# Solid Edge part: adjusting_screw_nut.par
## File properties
Title: Adjusting screw nut
Author: Abhinav Rai
Template: Normal.par
Last saved by: CADCIM
Revision: 19
Application: Solid Edge
Accuracy: 0.99
Material: aluminum
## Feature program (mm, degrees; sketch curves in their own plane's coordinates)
sketch for "unnamed RevolvedProtrusion 1" plane through (0, 0, 0) normal (0, -1, 0) x-axis (1, 0, 0)
  line (25.4, 9.7462) -> (74.676, 9.7462)
  line (76.2, 8.2222) -> (74.676, 9.7462)
  line (76.2, -26.8298) -> (76.2, 8.2222)
  line (76.2, -26.8298) -> (74.676, -28.3538)
  line (74.676, -28.3538) -> (47.625, -28.3538)
  line (47.625, -28.3538) -> (47.625, -60.1038)
  line (47.625, -60.1038) -> (25.4, -60.1038)
  line (25.4, -60.1038) -> (25.4, 9.7462)
revolve "unnamed RevolvedProtrusion 1" add full turn 360 deg
sketch for "Hole_1" plane through (76.2, 0, 0) normal (1, 0, 0) x-axis (0, 1, 0)
  hole centre (0, -9.3038) bore radius 9.5123
hole "Hole_1" diameter 19.0246 finite  VBottomAngle = 118 deg
pattern "unnamed Pattern 1" of "Hole_1"
pattern "unnamed Pattern 2"
sketch for "unnamed Cutout 1" plane through (0, 0, 9.7462) normal (0, 0, 1) x-axis (1, 0, 0)
extrude "unnamed Cutout 1" cut through along -normal
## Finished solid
Body 1: solid body, 16 faces, 16 edges, 4 vertices.
  Faces by surface: cylinder 7, cone 6, plane 3
  Edges by curve: circle 12, intersection 4
Bounding box of the edges (mm): 152.400 x 152.400 x 69.850, from (-76.2, -76.2, -60.1038) to (76.2, 76.2, 9.7462).
Cylindrical faces by radius (mm): R9.5123 x4, R38.1 x1, R47.625 x1, R76.2 x1
Conical faces (half-angle, radius in mm at the cone's reference point): 45 deg R74.676 x1, 45 deg R76.2 x1, 59 deg R9.5123 x4
Planar faces by outward normal: +z 1, -z 2
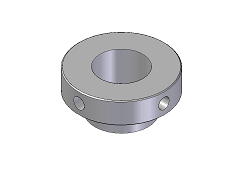
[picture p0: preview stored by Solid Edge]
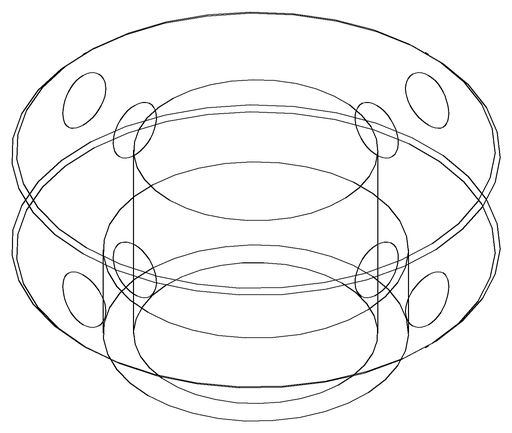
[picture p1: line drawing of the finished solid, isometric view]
